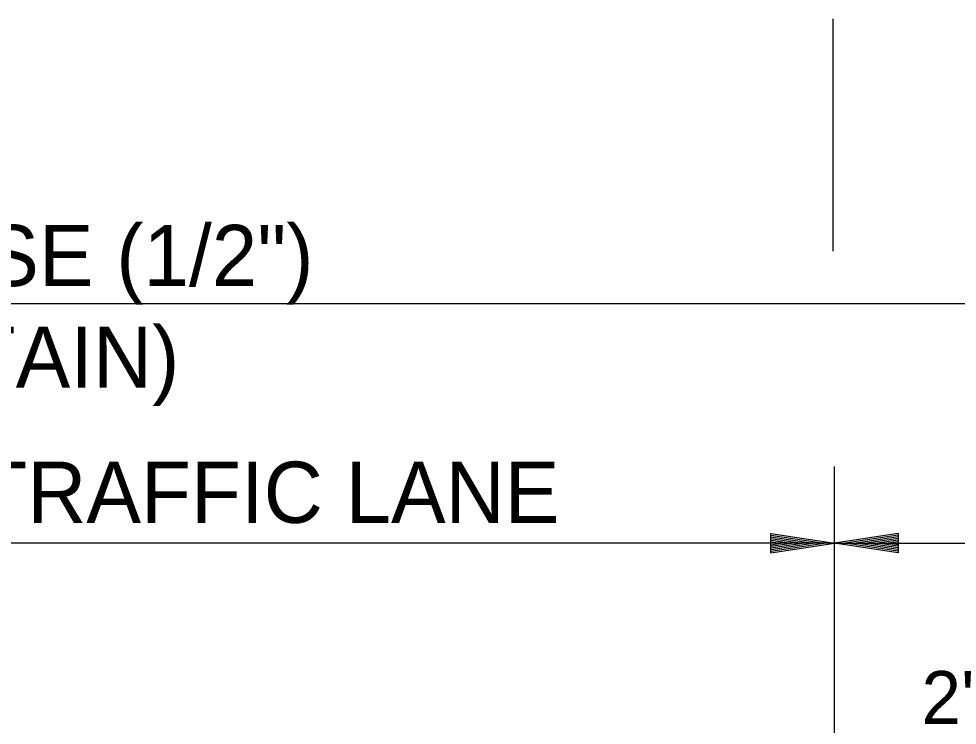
# Model space of a CAD drawing. Extents: x 1364961 to 1365294, y 367927 to 368034.
# Drawn here: x 1365047.54 to 1365056.37, y 367955.45 to 367962.1 of the extents above; entities that cross this region are included whole.
import ezdxf

# ---------------------------------------------------------------- set-up
doc = ezdxf.new("R2010")
doc.units = 0
doc.layers.add('Default', color=7, linetype='Continuous')

msp = doc.modelspace()

# ---------------------------------------------------------------- linework, layer by layer
at = {"layer": 'Default'}
for p, q in [((1365055.2031, 367959.9088), (1365055.2031, 367962.0969)), ((1365030.6735, 367959.4156), (1365055.7923, 367959.4156)), ((1365055.7923, 367959.4156), (1365065.1971, 367959.4156)), ((1365055.2141, 367954.3609), (1365055.2141, 367957.8843)), ((1365054.6141, 367957.2513), (1365055.2141, 367957.1613)), ((1365054.6141, 367957.0713), (1365054.6141, 367957.2513)), ((1365054.6141, 367957.2363), (1365055.1141, 367957.1613)), ((1365054.6141, 367957.2213), (1365055.0111, 367957.1613)), ((1365054.6141, 367957.2063), (1365054.9111, 367957.1613)), ((1365055.8141, 367957.2513), (1365055.2141, 367957.1613)), ((1365055.8141, 367957.2363), (1365055.3141, 367957.1613)), ((1365055.8141, 367957.2213), (1365055.4171, 367957.1613)), ((1365055.8141, 367957.2063), (1365055.5171, 367957.1613)), ((1365055.8141, 367957.2513), (1365055.8141, 367957.0713)), ((1365055.2141, 367957.1613), (1365043.2141, 367957.1613)), ((1365054.6141, 367957.1903), (1365054.8091, 367957.1613)), ((1365054.6141, 367957.1753), (1365054.7091, 367957.1613)), ((1365054.6141, 367957.0713), (1365055.2141, 367957.1613)), ((1365054.6141, 367957.1323), (1365054.8091, 367957.1613)), ((1365054.6141, 367957.1013), (1365055.0111, 367957.1613)), ((1365054.6141, 367957.0863), (1365055.1141, 367957.1613)), ((1365054.6141, 367957.1163), (1365054.9111, 367957.1613)), ((1365054.6141, 367957.1473), (1365054.7091, 367957.1613)), ((1365055.2141, 367957.1613), (1365065.1971, 367957.1613)), ((1365055.8141, 367957.0713), (1365055.2141, 367957.1613)), ((1365055.8141, 367957.0863), (1365055.3141, 367957.1613)), ((1365055.8141, 367957.1013), (1365055.4171, 367957.1613)), ((1365055.8141, 367957.1163), (1365055.5171, 367957.1613)), ((1365055.8141, 367957.1903), (1365055.6191, 367957.1613)), ((1365055.8141, 367957.1323), (1365055.6191, 367957.1613)), ((1365055.8141, 367957.1753), (1365055.7191, 367957.1613)), ((1365055.8141, 367957.1473), (1365055.7191, 367957.1613))]:
    msp.add_line(p, q, dxfattribs=at)

# ---------------------------------------------------------------- texts
for s, height, p in [('EXIST. 38\'-0" ACHM SURFACE COURSE (1/2")', 0.576, (1365033.7396, 367959.5808)), ('2" AVG. DEPTH - IN PLACE (RETAIN)', 0.576, (1365035.7225, 367958.6246)), ('12\'-0" TRAFFIC LANE', 0.576, (1365044.9712, 367957.3523)), ("2'", 0.5, (1365056.0333, 367955.4583))]:
    msp.add_text(s, height=height, dxfattribs=at).set_placement(p)

doc.saveas('drawing.dxf')
